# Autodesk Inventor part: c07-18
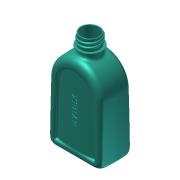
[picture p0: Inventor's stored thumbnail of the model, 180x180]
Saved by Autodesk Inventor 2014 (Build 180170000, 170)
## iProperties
Created: 2010-12
Part Number: c07-18
Material: Generic
Document SubType Name: Modeling
Designer: Beta-8540w
Density: 1 g/cm^3
Appearance: Ceramic
Author: Beta-8540w
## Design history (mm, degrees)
sketch "Sketch1"
  geometry: L1 (-25, 0)-(25, 0); L2 (25, 0)-(25, 80); L3 (25, 80)-(-25, 80); L4 (-25, 80)-(-25, 0); 2 further points
  constraints: 8 end point, 2 parallel, 1 coincident, 1 horizontal, 1 midpoint, 1 perpendicular
  dimensions: "d0" = 50 distance of L3.end L2.end; "d1" = 80 distance of L2.end L1.end
extrude "Extrusion1" new body sketch "Sketch1" distance "d2" = 15; taper "d3" = 0 deg
feature "FaceDraft1" dims angle "d4" = -2 deg
fillet "Fillet1"
fillet "Fillet2" dims "d5" = 8, "d6" = 8, "d7" = 8, "d8" = 8, "d9" = 8, "d10" = 8, "d11" = 3, "d12" = 3, "d13" = 3, "d14" = 6, "d15" = 5
sketch "Sketch2"
  geometry: L1 (5.522, 12)-(38.474, 12) reference; L2 (0, 0)-(43.996, 0) reference; L3 (41.757, 6.83)-(41.995, 0); L4 (41.925, 2)-(2.071, 2); L5 (2.001, 0)-(2.24, 6.83); L6 (5.522, 10)-(38.474, 10); A1 r 5.284 centre (38.474, 6.716) between (43.755, 6.9) and (38.474, 12) reference; A2 r 5.284 centre (5.522, 6.716) between (5.522, 12) and (0.241, 6.9) reference; A3 r 3.284 centre (38.474, 6.716) between (41.757, 6.83) and (38.474, 10); A4 r 3.284 centre (5.522, 6.716) between (5.522, 10) and (2.24, 6.83); 1 further point
  constraints: 8 end point, 4 point on circle, 4 point on line, 2 centre point, 1 other
  dimensions: "d16" = 2 radial gap between concentric circles of A2 A4
extrude "Extrusion2" cut sketch "Sketch2" distance "d17" = 3; taper "d18" = 0 deg
feature "FaceDraft2" dims angle "d19" = 15 deg
sketch "Sketch3" dims "d20" = 2.5
  geometry: L1 (16.476, 3)-(-16.476, 3) reference; L2 (16.476, 5.5)-(-16.476, 5.5); 9 further points
  constraints: 2 end point, 2 parallel, 1 horizontal alignment, 19 other
extrude "Extrusion3" cut sketch "Sketch3" distance "d21" = 3; taper "d22" = 0 deg
feature "FaceDraft3" dims angle "d23" = 10 deg
workplane "Work Plane1"
sketch "Sketch4"
  geometry: L1 (41.1, -1.222)-(41.476, -12) reference; L2 (41.476, -12)-(-8.524, -12) reference; L3 (-8.524, -12)-(-8.147, -1.222) reference; L4 (-3.776, 3)-(-1.272, 3) reference; L5 (-0.743, 0)-(33.695, 0) reference; L6 (34.225, 3)-(36.728, 3) reference; L7 (-11.024, -1.804)-(43.976, -1.804); A1 r 90 centre (16.476, -87.5) between (43.976, -1.804) and (-11.024, -1.804); 2 further points
  constraints: 2 end point, 2 point on circle, 1 centre point, 1 midpoint, 1 parallel, 1 vertical alignment, 4 other
  dimensions: "d25" = 90 radius of A1; "d26" = 14.5 distance edge to line of A1 L2; "d27" = 55 distance of L7.start L7.end
extrude_surface "ExtrusionSrf1" sketch "Sketch4" dims "d28" = 86, "d29" = 0
feature "Replace Face1"
fillet "Fillet3" dims "d34" = 1, "d35" = 2
mirror "Mirror1"
fillet "Fillet4" dims "d36" = 20
workplane "Work Plane3"
sketch "Sketch6"
  geometry: C1 r 9 at (0, 0); 1 further point
  constraints: 1 centre point, 1 coincident
  dimensions: "d38" = 18 diameter of C1
extrude "Top Boss" join sketch "Sketch6" distance "d39" = 16; taper "d40" = 0 deg
fillet "Fillet5" dims "d41" = 3
shell "Shell1" dims "d62" = 1
sketch "Sketch7"
  geometry: L1 (-9, 80.285)-(-9, 96) reference; C1 r 1 at (-9, 94.5); 1 further point
  constraints: 1 centre point, 1 point on line
  dimensions: "d42" = 1.5 distance of L1.end C1.centre; "d43" = 2 diameter of C1
coil "Coil2" sketch "Sketch7" pitch "d52" = 10; turns "d54" = 2; dims "d53" = 7, "d55" = 0, angle "d56" = 90 deg, angle "d57" = 90 deg, "d58" = 0, "d59" = 0
fillet "Fillet6" dims "d60" = 0.9
fillet "Fillet7" dims "d61" = 0.2
sketch "Sketch8"
  geometry: L1 (-9.664, 85.5)-(-11.164, 85.5); L2 (-11.164, 85.5)-(-11.164, 84.5); L3 (-11.164, 84.5)-(-9.664, 83.954); L4 (-9.664, 83.954)-(-9.664, 85.5); L5 (0.836, 2.555)-(0.836, 98.256); L6 (-9, 96)-(9, 96) reference; L7 (0, -19.758)-(0, 117.925) reference; 1 further point
  constraints: 10 end point, 2 parallel, 1 horizontal, 1 perpendicular
  dimensions: "d63" = 1 distance of L1.end L2.end; "d64" = 20 deg angle of L1 L3; "d65" = 10.5 distance between parallel lines of L6 L1; "d66" = 24 diameter of L2 L5; "d67" = 1.5 distance of L1.start L1.end
fillet "Fillet8"
revolve "Revolution1" stored, may be unused: angle "d69" = 90 deg
sketch "Sketch9"
  geometry: L1 (-3.222, 12.451)-(-3.222, 63.549); L2 (-3.222, 63.549)-(3.222, 63.549); L3 (3.222, 63.549)-(3.222, 12.451); L4 (3.222, 12.451)-(-3.222, 12.451); 3 further points
  constraints: 2 midpoint, 1 vertical, 1 vertical alignment, 2 other
  dimensions: "d70" = 38 vertical distance of point (0, 0) point (3.222, 38)
emboss "Emboss1" sketch "Sketch9" dims "d0" = 50, "d1" = 80, "d72" = 0.7, "d73" = 0
pattern_circular "Circular Pattern1" dims angle "d76" = 360 deg
feature "Rule Fillet1" dims "d74" = 0.1
body "Solid1"
body "Srf1"
node "Project Cut Edges1"
other parameters: "d68" = 90 deg
